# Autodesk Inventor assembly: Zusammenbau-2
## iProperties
Shininess: 64.0
Length Units: 11269
Angle Units: 11279
Time Units: 11290
Mass Units: 11283
Length Display Precision: 3
Angle Display Precision: 2
Compacted: True
Created: 2005-09
Part Number: Zusammenbau-2
Document SubType Name: Assembly
Designer: Frank
Manufacturer: Standard
Standards Organization: Custom
Density: 0.0
Volumn: 0.0
Area: 0.0
PropertySet Name: Model Information
Control State: 0
Master: False
Checked Out: False
Author: Frank
